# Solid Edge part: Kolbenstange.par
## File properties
Username: bmolnar
Dokumentum tartalom típus: 0
Author: bmolnar
Last saved by: bmolnar
Revision: 83
Sűrűség: 0,000 kg/m^3
Pontosság: 0,990
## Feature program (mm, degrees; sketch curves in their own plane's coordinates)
base feature "unnamed BaseFeature 1"
sketch for "unnamed Protrusion 1" plane through (-0.0012, 0, -18.75) normal (0, 0, -1) x-axis (0, -1, 0)
  circle centre (0, -0.0012) radius 31.5
extrude "unnamed Protrusion 1" add finite 9.35 along +normal
sketch for "Furat_1" plane through (0, 0, 41.0163) normal (0, 0, 1) x-axis (0, 1, 0)
  hole centre (0, 0) bore radius 3.3235
hole "Furat_1" nominal diameter 8 finite  VBottomAngle = 118 deg; ThreadDepth = 14.27 mm
chamfer "Letörés_1" setback 0.7  SetBackValue2 = 45 deg
sketch for "Kihúzás_3" #1 plane through (-0.0012, 0, -18.75) normal (0, 0, -1) x-axis (0, -1, 0)
  circle centre (0, -0.0012) radius 8
sketch for "Kihúzás_3" #2 plane through (-0.0012, 0, -18.75) normal (0, 0, -1) x-axis (0, -1, 0)
  circle centre (0, -0.0012) radius 31.5
extrude "Kihúzás_3" add finite 19.35 along -normal
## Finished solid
Body 1: solid body, 17 faces, 23 edges, 8 vertices.
  Faces by surface: plane 8, cylinder 5, cone 3, torus 1
  Edges by curve: circle 13, line 6, curve on surface 2, ellipse 2
Bounding box of the edges (mm; curved faces can reach further): 63.000 x 63.000 x 71.850, from (-31.5, -31.5, -28.1) to (31.5, 31.5, 43.75).
Cylindrical faces by radius (mm): R3.3235 x2, R4.125 x1, R8 x1, R31.5 x1
Conical faces (half-angle, radius in mm at the cone's reference point): 45 deg R4.0235 x1, 45 deg R4.225 x1, 59 deg R3.3235 x1
Toroidal faces (ring radius, tube radius in mm): R6.2 r1.8 x1
Planar faces by outward normal: +x 1, +z 3, -x 1, -z 1, oblique 2
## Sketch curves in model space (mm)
circle centre (0, 0, -18.75) radius 8
circle centre (0, 0, -18.75) radius 31.5
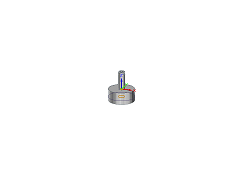
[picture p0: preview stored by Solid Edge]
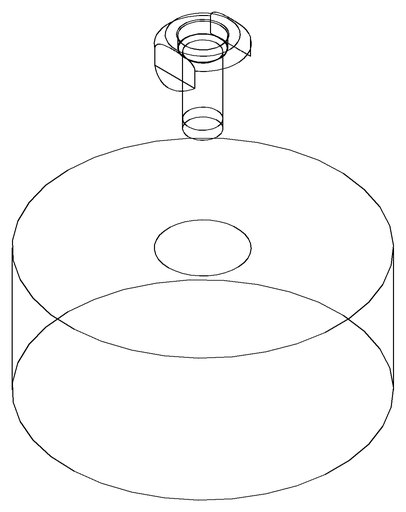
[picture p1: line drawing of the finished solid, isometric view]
